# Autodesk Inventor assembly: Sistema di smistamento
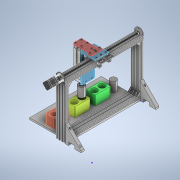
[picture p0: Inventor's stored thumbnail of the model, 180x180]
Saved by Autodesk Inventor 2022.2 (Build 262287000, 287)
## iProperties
Created: 2024-10
Part Number: Sistema di smistamento
Document SubType Name: Assembly
Designer: 18907419
Title: Sistema di smistamento.stp
Author: R5800u
Sending System: Autodesk Inventor 2025
Preprocessor: ST-DEVELOPER v20
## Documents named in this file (42)
- C:\Users\18907419\Desktop\automazione\smistamento\Sistema di smistamento.iam
- C:\Users\18907419\Desktop\automazione\smistamento\vslot-4020-verticaleipt.ipt
- C:\Users\18907419\Desktop\automazione\smistamento\Solido42.ipt
- C:\Users\18907419\Desktop\automazione\smistamento\Solido45.ipt
- C:\Users\18907419\Desktop\automazione\smistamento\Solido39.ipt
- C:\Users\18907419\Desktop\automazione\smistamento\Solido44.ipt
- C:\Users\18907419\Desktop\automazione\smistamento\Solido60.ipt
- C:\Users\18907419\Desktop\automazione\smistamento\Solido61.ipt
- C:\Users\18907419\Desktop\automazione\smistamento\Solido66.ipt
- C:\Users\18907419\Desktop\automazione\smistamento\Solido65.ipt
- C:\Users\18907419\Desktop\automazione\smistamento\Solido62.ipt
- C:\Users\18907419\Desktop\automazione\smistamento\Solido63.ipt
- C:\Users\18907419\Desktop\automazione\smistamento\Solido46.ipt
- C:\Users\18907419\Desktop\automazione\smistamento\Solido43.ipt
- C:\Users\18907419\Desktop\automazione\smistamento\Solido35.ipt
- C:\Users\18907419\Desktop\automazione\smistamento\Solido34.ipt
- C:\Users\18907419\Desktop\automazione\smistamento\Solido38.ipt
- C:\Users\18907419\Desktop\automazione\smistamento\Solido36.ipt
- C:\Users\18907419\Desktop\automazione\smistamento\Solido37.ipt
- C:\Users\18907419\Desktop\automazione\smistamento\Solido64.ipt
- C:\Users\18907419\Desktop\automazione\smistamento\Solido41.ipt
- C:\Users\18907419\Desktop\automazione\smistamento\Solido40.ipt
- C:\Users\18907419\Desktop\automazione\smistamento\Piatto guida.iam
- C:\Users\18907419\Desktop\automazione\smistamento\angolare_cilindro.ipt
- C:\Users\18907419\Desktop\automazione\smistamento\2600400100CP_100-A--.iam
- C:\Users\18907419\Desktop\automazione\smistamento\piastra_posteriore_cilindro.ipt
- C:\Users\18907419\Desktop\automazione\smistamento\Assieme_ventosa.iam
- C:\Users\18907419\Desktop\automazione\smistamento\vslot-4020-verticale-2.ipt
- C:\Users\18907419\Desktop\automazione\smistamento\piano_lavoro_1.ipt
- C:\Users\18907419\Desktop\automazione\smistamento\pezzo.ipt
- C:\Users\18907419\Desktop\automazione\smistamento\scatole_pezzi.ipt
- C:\Users\18907419\Desktop\automazione\smistamento\vslot-4020-orizzontale.ipt
- C:\Users\18907419\Desktop\automazione\smistamento\Cast Corner Bracket.ipt
- C:\Users\18907419\Desktop\automazione\smistamento\Cast Corner Bracket_MIR.ipt
- C:\Users\18907419\Desktop\automazione\smistamento\Cast Corner Bracket_MIR1.ipt
- C:\Users\18907419\Desktop\automazione\smistamento\Cast Corner Bracket_MIR_MIR.ipt
- C:\Users\18907419\Desktop\automazione\smistamento\AS 1420 - 1973 - M5 x 20.ipt
- C:\Users\18907419\Desktop\automazione\smistamento\AS 1420 - 1973 - M6 x 16.ipt
- C:\Users\18907419\Desktop\automazione\smistamento\AS 1420 - 1973 - M3 x 12.ipt
- C:\Users\18907419\Desktop\automazione\smistamento\BARRA FILETTATA T8.ipt
- C:\Users\18907419\Desktop\automazione\smistamento\sostegno laterale.ipt
- C:\Users\18907419\Desktop\automazione\smistamento\sostegno laterale_MIR.ipt
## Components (65 placed, 41 different names)
1. vslot-4020-verticaleipt:1
2. Solido42:1
3. Solido45:1
4. Solido39:1
5. Solido44:1
6. Solido60:1
7. Solido61:1
8. Solido66:1
9. Solido65:1
10. Solido62:1
11. Solido63:1
12. Solido46:1
13. Solido43:1
14. Solido35:1
15. Solido34:1
16. Solido38:1
17. Solido36:1
18. Solido37:1
19. Solido64:1
20. Solido41:1
21. Solido40:1
22. Piatto guida:1 [sub-assembly]
23. angolare_cilindro:1
24. 2600400100CP_100-A--:1 [sub-assembly]
25. piastra_posteriore_cilindro:1
26. Assieme_ventosa:1 [sub-assembly]
27. vslot-4020-verticale-2:1
28. vslot-4020-verticale-2:2
29. piano_lavoro_1:1
30. pezzo:1
31. scatole_pezzi:1
32. scatole_pezzi:2
33. scatole_pezzi:3
34. pezzo:2
35. vslot-4020-orizzontale:1
36. Cast Corner Bracket:3
37. Cast Corner Bracket:4
38. Cast Corner Bracket:11
39. Cast Corner Bracket_MIR:1
40. Cast Corner Bracket_MIR:2
41. Cast Corner Bracket_MIR:3
42. Cast Corner Bracket_MIR1:1
43. Cast Corner Bracket_MIR1:2
44. Cast Corner Bracket_MIR1:3
45. Cast Corner Bracket_MIR_MIR:1
46. Cast Corner Bracket_MIR_MIR:2
47. Cast Corner Bracket_MIR_MIR:3
48. AS 1420 - Metrico M5 x 20:1
49. AS 1420 - Metrico M5 x 20:2
50. AS 1420 - Metrico M5 x 20:3
51. AS 1420 - Metrico M5 x 20:4
52. AS 1420 - Metrico M5 x 20:5
53. AS 1420 - Metrico M5 x 20:6
54. AS 1420 - Metrico M5 x 20:7
55. AS 1420 - Metrico M5 x 20:8
56. AS 1420 - Metrico M5 x 20:9
57. AS 1420 - Metrico M5 x 20:10
58. AS 1420 - Metrico M5 x 20:11
59. AS 1420 - Metrico M5 x 20:12
60. AS 1420 - Metrico M6 x 16:1
61. AS 1420 - Metrico M6 x 16:2
62. AS 1420 - Metrico M3 x 12:1
63. BARRA FILETTATA T8:1
64. sostegno laterale:2
65. sostegno laterale_MIR:1
